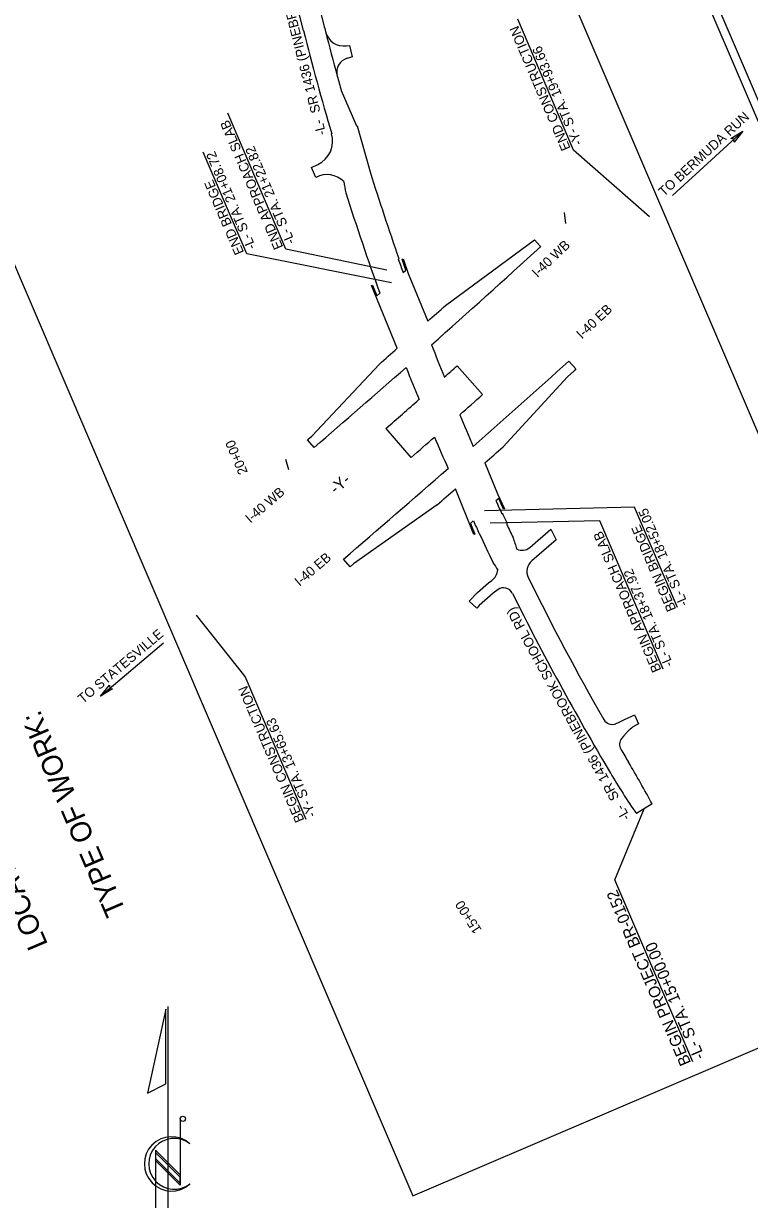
# Model space of a CAD drawing. Extents: x 1550250 to 1553148, y 808916 to 812359.
# Drawn here: x 1551395 to 1552151, y 809907 to 811132 of the extents above; entities that cross this region are included whole.
import ezdxf

# ---------------------------------------------------------------- set-up
doc = ezdxf.new("R2010")
doc.units = 0
for name, color, linetype in [('P_RDY_DSN_Text', 7, 'Continuous'), ('P_RDY_Shade_Light', 7, 'Continuous'), ('Prop DSN Text', 7, 'Continuous'), ('Prop Terminator Cell', 7, 'Continuous'), ('Sheet_North_Arrow_CELL', 7, 'Continuous'), ('Sheet_Plan_CELL', 7, 'Continuous'), ('Sheet_Title_CELL', 7, 'Continuous')]:
    doc.layers.add(name, color=color, linetype=linetype)

msp = doc.modelspace()

# ---------------------------------------------------------------- linework, layer by layer
at = {"layer": 'P_RDY_DSN_Text'}
for points in [[(1552046.5, 810930.6), (1551967.3, 811000.3), (1551909.6, 811136.6)], [(1551773.1, 810875.2), (1551668, 810897.1), (1551607.5, 811038.6)], [(1551777.9, 810862), (1551627.2, 810892.1), (1551581.9, 810998.1)], [(1552075.7, 810523.7), (1552030.9, 810628.3), (1551874.9, 810624.4)], [(1552060.7, 810459.7), (1551994.7, 810614), (1551880.8, 810611.6)], [(1551689.2, 810303.2), (1551625.5, 810452.1), (1551575, 810515.9)], [(1552091.7, 810050.5), (1552010.4, 810240.3), (1552041.1, 810314.3)]]:
    msp.add_lwpolyline(points, dxfattribs=at)
at = {"layer": 'P_RDY_Shade_Light'}
for p, q in [((1551959.5, 810923.8), (1551958, 810935.1)), ((1551785.5, 810887.4), (1551784.9, 810886.9)), ((1551846.2, 810775.5), (1551872.7, 810745.6)), ((1551798.5, 810680.2), (1551772.2, 810710.3)), ((1551667.4, 810678.5), (1551670.7, 810667.5)), ((1551892.8, 810621.5), (1551893.3, 810622)), ((1551898.4, 810611.1), (1551897.8, 810610.8)), ((1552049.2, 810319.3), (1552032.9, 810309.2))]:
    msp.add_line(p, q, dxfattribs=at)
for points in [[(1551686.2, 811124.8), (1551670.5, 811186.4), (1551659.6, 811235.2), (1551678.4, 811240), (1551691.9, 811191.8), (1551707.5, 811130.3)], [(1551731.2, 811108.8), (1551734.2, 811109.2), (1551737, 811097.3), (1551731.7, 811095.8)], [(1551731.2, 811108.8), (1551734.2, 811109.2), (1551737, 811097.3), (1551731.7, 811095.8)], [(1551725.6, 811062.3), (1551741.4, 811025.4), (1551742, 811025.6), (1551755.6, 810977.5)], [(1551699.2, 810971.6), (1551694.7, 810982.2), (1551701.1, 810985.2)], [(1551834.1, 810838.5), (1551926.9, 810906.7), (1551933.2, 810899.7)], [(1551790, 810872.6), (1551793, 810875.3), (1551789, 810886.6), (1551789.9, 810886.9), (1551795.3, 810871.7), (1551815.6, 810822)], [(1551783.9, 810793.8), (1551757.2, 810859.3), (1551758.1, 810859.6), (1551762.6, 810848.5), (1551765.8, 810851.3)], [(1551697.3, 810690.4), (1551690.4, 810698.5), (1551691.2, 810699.2), (1551694.9, 810702.4), (1551765.3, 810777.4)], [(1551962.6, 810780.5), (1551970, 810772.3), (1551968, 810770.4), (1551961.2, 810764.2), (1551894.1, 810691.1)], [(1551875.2, 810674.4), (1551888.4, 810642.1), (1551895.5, 810626.7), (1551894.6, 810626.3), (1551889.5, 810637.3), (1551886.6, 810634.8)], [(1551863.1, 810614.1), (1551860.1, 810611.4), (1551864.7, 810600.3), (1551863.7, 810599.9), (1551844.4, 810647.3)], [(1551825.4, 810630.7), (1551738.4, 810569.4), (1551734.8, 810566.3), (1551727.9, 810574.3)], [(1551921.8, 810586.4), (1551943.7, 810605.5), (1551949.2, 810594.3), (1551924.1, 810572.5)], [(1551888.9, 810542.6), (1551883.8, 810538.9), (1551869.3, 810526), (1551866.7, 810523.3), (1551858.8, 810530.6), (1551867.3, 810539.6), (1551879, 810549.5), (1551882.3, 810552)], [(1552011.4, 810402.9), (1552013.5, 810403.7), (1552020.4, 810407.1), (1552028.3, 810410.7), (1552031, 810411.9), (1552035, 810402.7), (1552032.4, 810401.3), (1552031.8, 810401), (1552031.3, 810400.7), (1552030.7, 810400.3), (1552030.2, 810400), (1552029.5, 810399.5), (1552028.9, 810399.1), (1552027.7, 810398.3), (1552026.4, 810397.2), (1552025.4, 810396.2), (1552024.7, 810395.6), (1552024.3, 810395.1), (1552023.8, 810394.7), (1552023.3, 810394.1), (1552023, 810393.8), (1552019.5, 810389.7), (1552017.8, 810387.6)]]:
    msp.add_lwpolyline(points, dxfattribs=at)
for centre, radius, start, end in [((1554524.2, 811845.1), 2928, 194.2411, 196.4227), ((1554524.2, 811845.1), 2906, 194.2411, 194.3747), ((1551728.5, 811128.7), 20, 194.3747, 277.7813), ((1554524.2, 811845.1), 2906, 194.3747, 195.3183), ((1551728.5, 811128.7), 20, 194.3747, 277.7813), ((1551735.9, 811081.4), 15, 106, 195.318), ((1551735.9, 811081.4), 15, 106, 195.3183), ((1554524.2, 811845.1), 2906, 195.3183, 195.6275), ((1551689.7, 811009.7), 27, 294.9692, 16.4227), ((1551710.9, 810950.7), 24, 44.141, 119.2133), ((1554524.2, 811845.1), 2901.3, 197.4005, 199.2759), ((1554591.1, 811489.5), 2910.2, 190.3357, 190.5682), ((1554524.2, 811845.1), 2932, 197.6574, 199.8143), ((1544245.7, 819324.7), 11405.2, 311.61158, 312.37947), ((1554524.2, 811845.1), 2902, 199.2813, 199.5795), ((1544245.7, 819324.7), 11384.2, 311.6783, 311.80331), ((1544245.7, 819324.7), 11384.2, 311.34006, 311.46505), ((1554524.2, 811845.1), 2900.4, 201.1755, 201.8905), ((1544245.7, 819324.7), 11513.2, 311.4234, 312.08736), ((1544245.7, 819324.7), 11405.2, 310.79503, 311.43356), ((1554524.2, 811845.1), 2933.6, 201.4162, 202.1212), ((1544245.7, 819324.7), 11439.2, 311.54934, 311.63796), ((1544245.7, 819324.7), 11439.2, 311.14409, 311.37272), ((1544245.7, 819324.7), 11479.2, 311.47967, 311.63796), ((1554524.2, 811845.1), 2900.4, 202.7273, 203.435), ((1544245.7, 819324.7), 11479.2, 311.14431, 311.30461), ((1554524.2, 811845.1), 2933.6, 202.9465, 203.6447), ((1544243.9, 819329.1), 11538.7, 311.40434, 311.52928), ((1544245.7, 819324.7), 11513.2, 310.53288, 311.24961), ((1544243.9, 819329.1), 11538.7, 311.07551, 311.20049), ((1554524.2, 811845.1), 2902, 204.6502, 204.9387), ((1554524.2, 811845.1), 2901.3, 204.9348, 205.1722), ((1554524.2, 811845.1), 2932, 204.8269, 205.1121), ((1554524.2, 811845.1), 2902, 205.1721, 205.4792), ((1554524.2, 811845.1), 2932, 205.1121, 205.7625), ((1554653.7, 811503.3), 2894.9, 198.2497, 198.4992), ((1551913.9, 810595.4), 12, 242.6337, 311.0211), ((1554332.7, 812152.3), 2915.4, 212.8525, 213.0366), ((1551933.9, 810561.2), 15, 131.0211, 204.3749), ((1551872.2, 810565.3), 16.7, 307.4014, 351.9162), ((1551894.7, 810534.4), 10, 26.4952, 125.582), ((1554524.2, 811845.1), 2906, 206.3571, 209.6587), ((1554524.2, 811845.1), 2928, 206.4952, 210.6719), ((1552007.6, 810412.1), 10, 209.6587, 292.2996), ((1552025.4, 810381.2), 10, 140.1663, 210.365), ((1554524.2, 811845.1), 2906, 210.365, 210.6719), ((1551064.6, 809793.3), 1116.3, 28.1132, 30.6719), ((1552636.7, 810725.7), 733.5, 210.6719, 214.5933)]:
    msp.add_arc(centre, radius, start, end, dxfattribs=at)
at = {"layer": 'Prop DSN Text'}
for p, q in [((1552070.5, 810952.8), (1552143.6, 811020.1)), ((1551474.8, 810431.6), (1551540.6, 810486.9))]:
    msp.add_line(p, q, dxfattribs=at)
at = {"layer": 'Prop Terminator Cell'}
for points in [[(1552131.4, 811012.2), (1552143.6, 811020.1), (1552134.7, 811008.4), (1552134.3, 811011.6)], [(1551487.4, 810439), (1551474.8, 810431.6), (1551484.2, 810442.9), (1551484.5, 810439.7)]]:
    msp.add_lwpolyline(points, close=True, dxfattribs=at)
at = {"layer": 'Sheet_North_Arrow_CELL'}
for p, q in [((1551545.3, 809772), (1551545.3, 810108.4)), ((1551558, 809991.3), (1551558, 809922.3)), ((1551558, 809933), (1551532.3, 809958.8)), ((1551532.3, 809958.8), (1551532.3, 809888.6)), ((1551558, 809930.5), (1551532.3, 809956.2)), ((1551532.3, 809956.2), (1551532.3, 809949.9)), ((1551567.5, 809965.6), (1551567.9, 809965.3)), ((1551558, 809924.2), (1551532.3, 809949.9)), ((1551532.3, 809949.9), (1551558, 809924.2)), ((1551558, 809922.3), (1551532.3, 809948)), ((1551558, 809924.2), (1551558, 809930.5))]:
    msp.add_line(p, q, dxfattribs=at)
msp.add_lwpolyline([(1551543, 810105.4), (1551523.8, 810018.1), (1551543, 810027.8)], close=True, dxfattribs=at)
msp.add_circle((1551560.7, 809991.3), 2.74, dxfattribs=at)
for centre, radius, start, end in [((1551548.9, 809944.4), 28.3, 47.84, 312.3941), ((1551551.6, 809944.4), 26.5, 53.095, 308.6287)]:
    msp.add_arc(centre, radius, start, end, dxfattribs=at)
at = {"layer": 'Sheet_Plan_CELL'}
msp.add_lwpolyline([(1551190.2, 811336.1), (1551800.2, 809911.1), (1552391.4, 810164.1), (1551781.4, 811589.2)], close=True, dxfattribs=at)
at = {"layer": 'Sheet_Title_CELL'}
for p, q in [((1552747.8, 809656.4), (1551686.1, 812136.6)), ((1552266.8, 810801.6), (1552059.9, 811285.3))]:
    msp.add_line(p, q, dxfattribs=at)

# ---------------------------------------------------------------- texts
at = {"layer": 'P_RDY_DSN_Text'}
for s, height, rotation, p in [('-L-  SR 1436 (PINEBROOK SCHOOL RD)', 10, 104.2411, (1551709.9, 811017.1)), ('END CONSTRUCTION', 10, 113.1736, (1551964.6, 811002.2)), ('-Y- STA. 19+93.66', 10, 113.1736, (1551977, 811007.5)), ('END APPROACH SLAB', 10, 113.1736, (1551665.3, 810899.3)), ('-L- STA. 21+08.72', 10, 113.1736, (1551636.9, 810899.1)), ('-L- STA. 21+22.82', 10, 113.1736, (1551677.7, 810904.6)), ('END BRIDGE', 10, 113.1736, (1551624.5, 810893.8)), ('I-40 WB', 10, 43.4476, (1551929.7, 810867)), ('I-40 EB', 10, 43.2289, (1551976.1, 810802.9)), ('20+00', 10, 113.1736, (1551628.5, 810664.8)), ('-Y-', 12, 40.8561, (1551720, 810641.3)), ('I-40 WB', 10, 40.7759, (1551631, 810611.1)), ('-L- STA. 18+52.05', 10, 113.1736, (1552086.9, 810527.5)), ('BEGIN BRIDGE', 10, 113.1736, (1552074.5, 810522.2)), ('BEGIN APPROACH SLAB', 10, 113.1736, (1552059.1, 810458.9)), ('I-40 EB', 10, 40.5572, (1551682.2, 810545.4)), ('-L- STA. 18+37.92', 10, 113.1736, (1552071.5, 810464.3)), ('-L-  SR 1436 (PINEBROOK SCHOOL RD)', 10, 118.8173, (1552026.8, 810305.2)), ('BEGIN CONSTRUCTION', 10, 113.1736, (1551687.4, 810302.5)), ('-Y- STA. 13+65.63', 10, 113.1736, (1551699.8, 810307.8)), ('BEGIN PROJECT BR-0152', 12, 113.1736, (1552090, 810049.7)), ('15+00', 10, 122.621, (1551872.2, 810188.2)), ('-L- STA. 15+00.00', 12, 113.1736, (1552104.3, 810055.8))]:
    msp.add_text(s, height=height, rotation=rotation, dxfattribs=at).set_placement(p)
at = {"layer": 'Prop DSN Text'}
for s, rotation, p in [('TO BERMUDA RUN', 42.6287, (1552061.6, 810951.3)), ('TO STATESVILLE', 40.1021, (1551456.6, 810423.3))]:
    msp.add_text(s, height=10, rotation=rotation, dxfattribs=at).set_placement(p)
at = {"layer": 'Sheet_Title_CELL'}
for s, height, p in [('TYPE OF WORK:', 21.563, (1551501.6, 810207.6)), ('LOCATION: ', 21.56, (1551420.5, 810172.9))]:
    msp.add_text(s, height=height, rotation=113.1736, dxfattribs=at).set_placement(p)

doc.saveas('drawing.dxf')
